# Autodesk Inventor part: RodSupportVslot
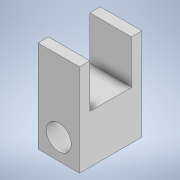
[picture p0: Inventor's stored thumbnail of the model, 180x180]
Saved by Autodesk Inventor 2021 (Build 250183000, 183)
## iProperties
Created: 2026-10
Part Number: RodSupportVslot
Material: Generic
Document SubType Name: Modeling
Designer: hp
Density: 1 g/cm^3
Appearance: Default
Author: hp
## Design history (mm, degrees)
sketch "Sketch1"
  geometry: L1 (10, -10)-(-10, -10); L2 (-10, -10)-(-10, 13.256); L3 (-10, 13.256)-(10, 13.256); L4 (10, 13.256)-(10, -10); L5 (-10, 13.256)-(10, 13.256); L6 (10, 13.256)-(10, 34.256); L7 (10, 34.256)-(-10, 34.256); L8 (-10, 34.256)-(-10, 13.256); C1 r 6 at (0, 0); 3 further points
  constraints: 16 end point, 4 parallel, 2 horizontal, 2 perpendicular, 1 centre point, 1 coincident
  dimensions: "d39" = 12 diameter of C1; "d40" = 20 distance of L2.end L3.end; "d42" = 20 distance of L7.end L6.end; "d48" = 10 distance from line of L1 point (0, 0); "d49" = 13.256 distance from line of L3 point (0, 0); "d50" = 21 distance of L5.end L6.end
extrude "Extrusion3" new body sketch "Sketch1" stored distance "d44" = 30; taper "d45" = 0 deg
extrude "Extrusion4" cut sketch "Sketch1" stored distance "d46" = 20; taper "d47" = 0 deg
body "Solid2"
